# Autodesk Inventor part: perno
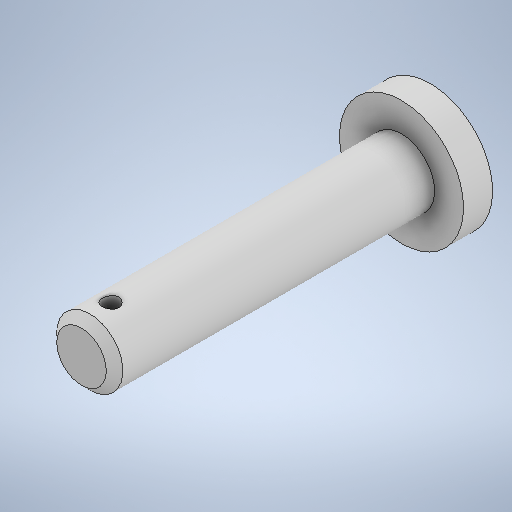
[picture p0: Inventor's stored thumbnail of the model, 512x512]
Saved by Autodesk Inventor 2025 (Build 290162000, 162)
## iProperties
Created: 2025-10
Part Number: perno
Material: Generico
Document SubType Name: Modeling
Designer: 18619647
Density: 1 g/cm^3
Appearance: Default
Author: 18619647
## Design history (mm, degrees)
sketch "Schizzo1"
  geometry: C1 r 7.5 at (0, 0); 1 further point
  constraints: 1 centre point, 1 coincident
  dimensions: "d0" = 15 diameter of C1
extrude "Estrusione1" new body sketch "Schizzo1" distance "d1" = 3.5; taper "d2" = 0 deg
sketch "Schizzo2"
  geometry: C1 r 4 at (0, 0); 1 further point
  constraints: 1 centre point, 1 coincident
  dimensions: "d3" = 8 diameter of C1
extrude "Estrusione2" join sketch "Schizzo2" distance "d4" = 42.2; taper "d5" = 0 deg
chamfer "Smusso1" distance "d6" = 1; stored, may be unused: second distance "d7" = 2, angle "d8" = 45 deg
node "Piano di lavoro1"
sketch "Schizzo3"
  geometry: L1 (-6.344, 0)-(-6.344, 3.5) reference; L2 (-6.344, 3.5)-(0, 3.5) reference; L3 (0, 3.5)-(0, 41.2) reference; L4 (6.344, 0)-(-6.344, 0) reference; L5 (6.344, 3.5)-(6.344, 0) reference; L6 (0, 3.5)-(6.344, 3.5) reference; L7 (0, 3.5)-(0, 38.7); C1 r 1 at (0, 38.7); 1 further point
  constraints: 2 end point, 1 centre point, 1 coincident, 1 point on line
  dimensions: "d10" = 35.2 distance of L2.end L7.end; "d11" = 2 diameter of C1
extrude "Estrusione3" cut sketch "Schizzo3" extent not by distance; stored distance "d12" = 0; taper "d13" = 0 deg
node "Piano di lavoro2"
sketch "Schizzo4"
  geometry: L1 (-6.344, 0)-(-6.344, 3.5) reference; L2 (-6.344, 3.5)-(0, 3.5) reference; L3 (0, 3.5)-(0, 41.2) reference; L4 (6.344, 0)-(-6.344, 0) reference; L5 (6.344, 3.5)-(6.344, 0) reference; L6 (0, 3.5)-(6.344, 3.5) reference; L7 (0, 3.5)-(0, 5); 1 further point
  constraints: 2 end point, 1 point on line
  dimensions: "d15" = 1.5 distance of L2.end L7.end
hole "Foro1" sketch "Schizzo4" at (0, 5) diameter "d16" = 3; stored, may be unused: countersink angle "d20" = 90 deg, drill point angle "d22" = 118 deg; dims "d17" = 6, "d18" = 4, "d19" = 2, "d21" = 2
node "Solido1"
node "Proietta spigoli di taglio1"
node "Proietta spigoli di taglio2"
other parameters: "d9" = 4, "d14" = -4
